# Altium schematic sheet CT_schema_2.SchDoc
size 294 x 169 mm
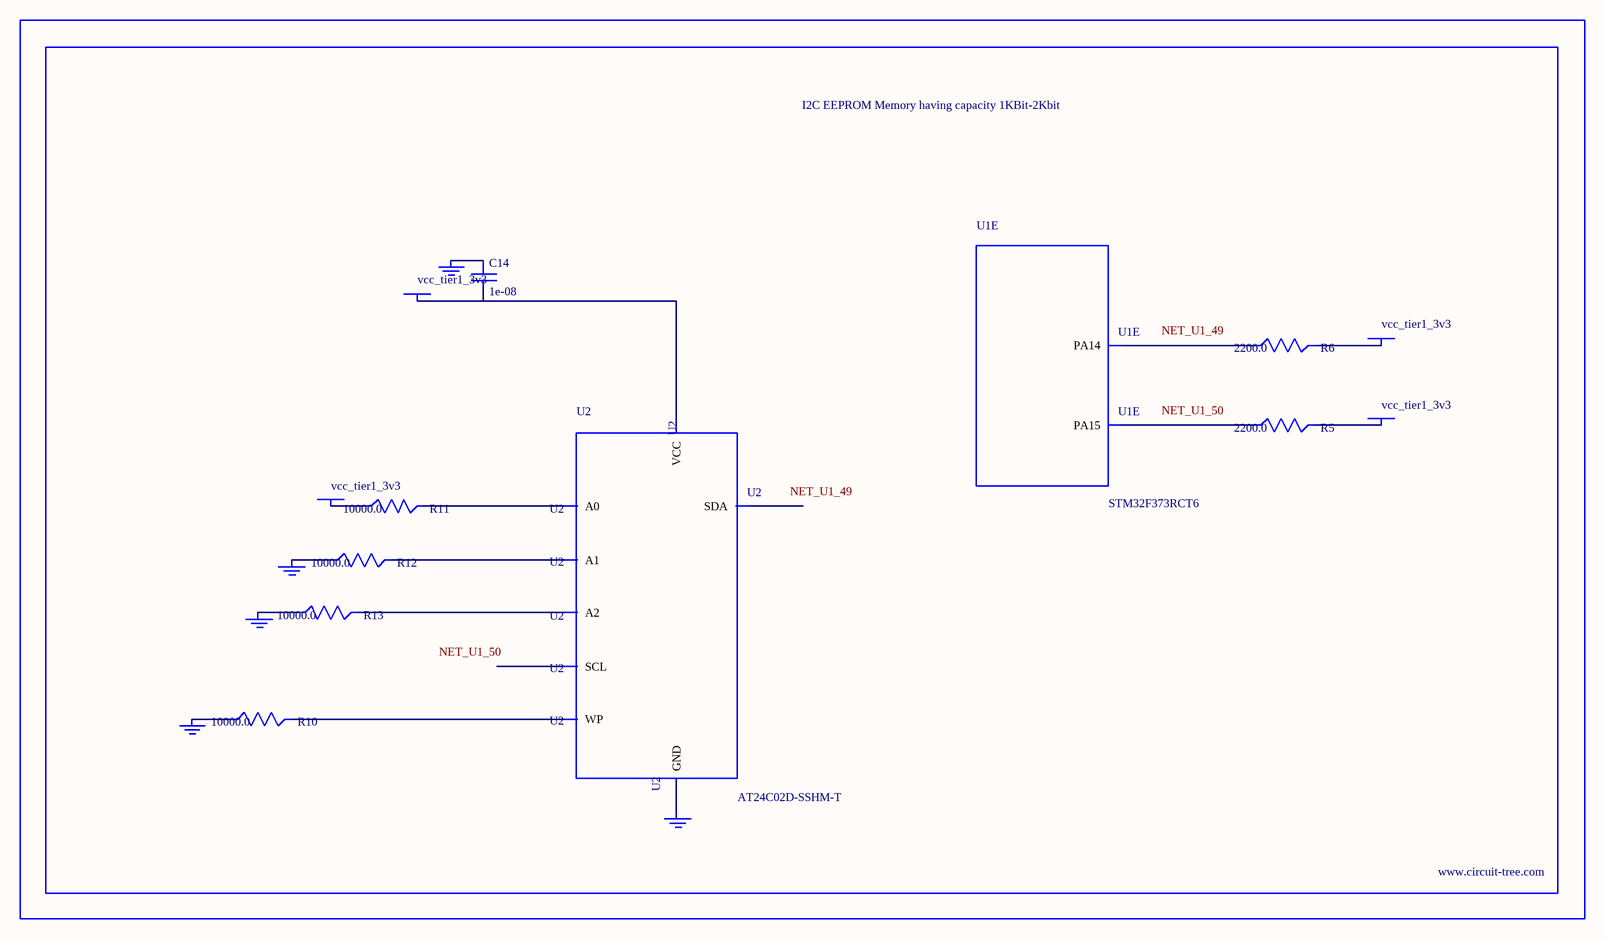
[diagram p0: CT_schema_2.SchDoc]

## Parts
BORDER1  (no value)
C14  1e-08  [C0402]
GND_INSTANCE_1_0  (no value)
GND_INSTANCE_1_1  (no value)
GND_INSTANCE_1_2  (no value)
GND_INSTANCE_1_3  (no value)
GND_INSTANCE_1_4  (no value)
POWER_INSTANCE_1_0  vcc_tier1_3v3
POWER_INSTANCE_1_1  vcc_tier1_3v3
POWER_INSTANCE_1_2  vcc_tier1_3v3
POWER_INSTANCE_1_3  vcc_tier1_3v3
R5  2200.0  [R0603]
R6  2200.0  [R0603]
R10  10000.0  [R0603]
R11  10000.0  [R0603]
R12  10000.0  [R0603]
R13  10000.0  [R0603]
U1  STM32F373RCT6  [LQFP64]  (part E of 8)
U2  AT24C02D-SSHM-T  [AT24C02D]

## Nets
NetC14_1: C14.1 GND_INSTANCE_1_3.0(GND)
NetC14_2: C14.2 POWER_INSTANCE_1_1.0(PWR) U2.8(VCC)
NetGND_INSTANCE_1_0_0: GND_INSTANCE_1_0.0(GND) R12.1
NetGND_INSTANCE_1_1_0: GND_INSTANCE_1_1.0(GND) R13.1
NetGND_INSTANCE_1_2_0: GND_INSTANCE_1_2.0(GND) R10.1
NetGND_INSTANCE_1_4_0: GND_INSTANCE_1_4.0(GND) U2.4(GND)
NetPOWER_INSTANCE_1_0_0: POWER_INSTANCE_1_0.0(PWR) R11.1
NetPOWER_INSTANCE_1_2_0: POWER_INSTANCE_1_2.0(PWR) R6.2
NetPOWER_INSTANCE_1_3_0: POWER_INSTANCE_1_3.0(PWR) R5.2
NetR5_1: R5.1 U1.50(PA15)
NetR6_1: R6.1 U1.49(PA14)
NetR10_2: R10.2 U2.7(WP)
NetR11_2: R11.2 U2.1(A0)
NetR12_2: R12.2 U2.2(A1)
NetR13_2: R13.2 U2.3(A2)

Not connected (* = marked no-connect by the designer): U2 5(SDA) 6(SCL)

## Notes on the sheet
- Labels drawn without touching a wire or pin: NET_U1_49, NET_U1_50

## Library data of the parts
BORDER1 = BORDER_PAGE1
C14 = C0402C103K3RAC
GND_INSTANCE_1_0-GND_INSTANCE_1_4 = GND
POWER_INSTANCE_1_0-POWER_INSTANCE_1_3 = PWR
R5 R6 = RC0603JR-072K2L
R10-R13 = RC0603JR-0710KL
